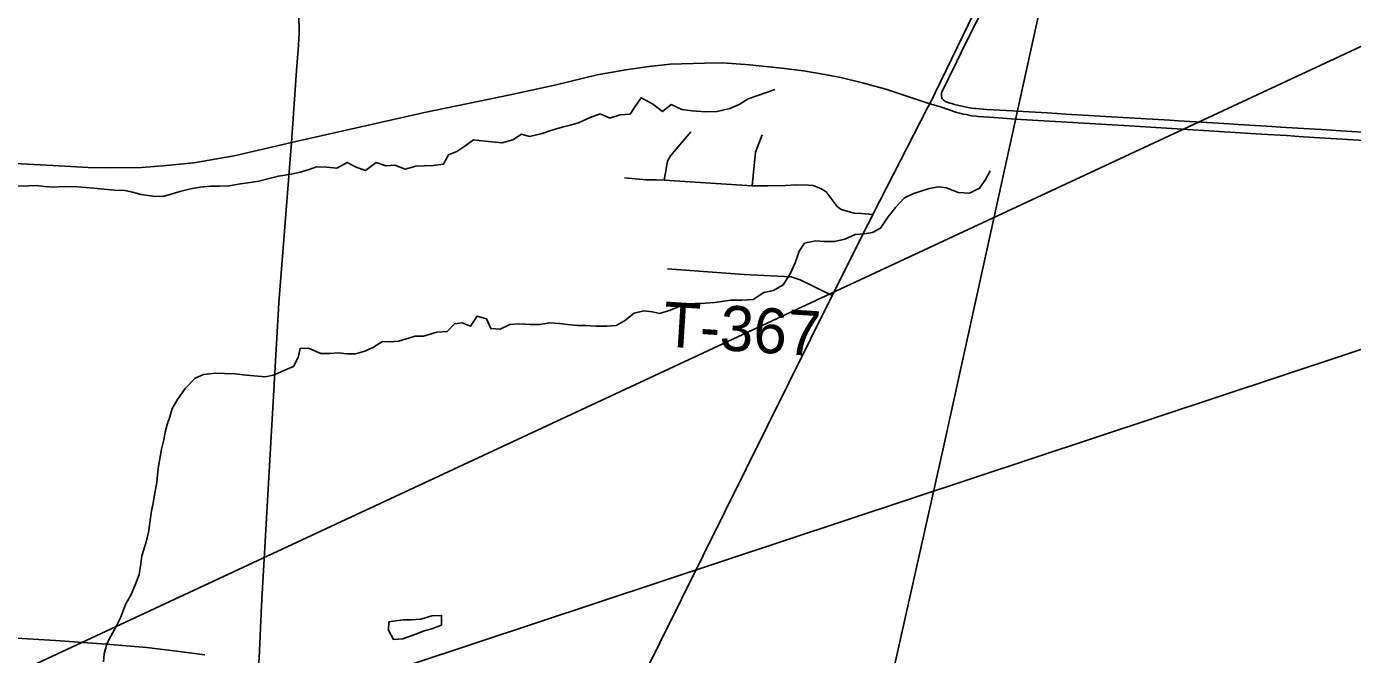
# Model space of a CAD drawing. Extents: x 0 to 34, y 0 to 22.
# Drawn here: x 7.93 to 9.603, y 7.332 to 8.125 of the extents above; entities that cross this region are included whole.
import ezdxf

# ---------------------------------------------------------------- set-up
doc = ezdxf.new("R2010")
doc.units = 0
for name, color, linetype in [('GM_X_City_Street', 7, 'Continuous'), ('GM_X_Corporation', 7, 'Continuous'), ('GM_X_County_Road', 7, 'Continuous'), ('GM_X_Minor_Lake', 7, 'Continuous'), ('GM_X_Minor_River', 7, 'Continuous'), ('GM_X_Rail_Line', 7, 'Continuous'), ('GM_X_State_Route', 7, 'Continuous'), ('GM_X_Township_Road', 7, 'Continuous'), ('GM_X_Township_Road_Text', 7, 'Continuous'), ('SH_Text', 7, 'Continuous')]:
    doc.layers.add(name, color=color, linetype=linetype)

msp = doc.modelspace()

# ---------------------------------------------------------------- linework, layer by layer
at = {"layer": 'GM_X_City_Street'}
for points in [[(8.9746, 7.8897), (8.9836, 7.8891), (8.9982, 7.888)], [(8.8949, 7.809), (8.9064, 7.8054), (8.9466, 7.7856)]]:
    msp.add_lwpolyline(points, dxfattribs=at)
at = {"layer": 'GM_X_Corporation'}
msp.add_lwpolyline([(9.6236, 7.9915), (9.5883, 7.9936), (9.5711, 7.9947), (9.5126, 7.9983), (9.5015, 7.9989), (9.4598, 8.0014), (9.441, 8.0026), (9.384, 8.0061), (9.3731, 8.0068), (9.2923, 8.0117), (9.2419, 8.0147), (9.2305, 8.0154), (9.218, 8.0161), (9.1877, 8.0179), (9.1818, 8.0183), (9.1813, 8.0183), (9.1749, 8.0187), (9.1419, 8.0206), (9.1329, 8.0212), (9.1291, 8.0215), (9.1266, 8.0218), (9.1227, 8.0223), (9.1202, 8.0227), (9.1164, 8.0233), (9.1125, 8.0241), (9.1088, 8.0249), (9.105, 8.0258), (9.1012, 8.0268), (9.0976, 8.0279), (9.0951, 8.0286), (9.0907, 8.0301), (9.0902, 8.0303), (9.0895, 8.0307), (9.0889, 8.031), (9.0882, 8.0316), (9.0877, 8.0319), (9.0872, 8.0325), (9.0864, 8.0334), (9.086, 8.034), (9.0857, 8.0345), (9.0852, 8.0357), (9.085, 8.0362), (9.0848, 8.0369), (9.0847, 8.0381), (9.0846, 8.0387), (9.0846, 8.0394), (9.0847, 8.0402), (9.0848, 8.0409), (9.0849, 8.0414), (9.0852, 8.0422), (9.0856, 8.0431), (9.0937, 8.0597), (9.1042, 8.0812), (9.1152, 8.1037), (9.1431, 8.1596)], dxfattribs=at)
at = {"layer": 'GM_X_County_Road'}
msp.add_line((8.2551, 7.8616), (8.2644, 7.9787), dxfattribs=at)
for points in [[(8.2731, 8.1015), (8.2742, 8.1169), (8.2738, 8.1415), (8.2719, 8.1531), (8.2681, 8.1637), (8.2587, 8.1797), (8.2463, 8.197), (8.2278, 8.2218), (8.2228, 8.2286)], [(8.2644, 7.9787), (8.2708, 8.0698), (8.2731, 8.1015)], [(8.2644, 7.9787), (8.4323, 8.0168), (8.5402, 8.0389), (8.5984, 8.0514), (8.6501, 8.064), (8.6862, 8.0705), (8.7154, 8.0746), (8.7423, 8.0777), (8.7857, 8.0791), (8.8088, 8.0794), (8.8424, 8.0766), (8.8833, 8.0728), (8.9106, 8.0693), (8.9375, 8.0647), (8.9578, 8.0609), (8.9851, 8.0542), (9.0145, 8.0462), (9.0386, 8.0381), (9.0699, 8.0276)], [(7.8672, 7.9559), (7.923, 7.9516), (7.9711, 7.9491), (8.0078, 7.9471), (8.0344, 7.9466), (8.075, 7.9471), (8.1021, 7.9491), (8.1413, 7.9531), (8.1919, 7.9621), (8.2644, 7.9787)], [(8.2165, 7.2479), (8.2194, 7.2772), (8.2237, 7.3274), (8.2266, 7.3943), (8.2484, 7.7765), (8.2551, 7.8616)]]:
    msp.add_lwpolyline(points, dxfattribs=at)
at = {"layer": 'GM_X_Minor_Lake'}
for points in [[(8.4536, 7.3742), (8.4538, 7.3816), (8.4417, 7.3812), (8.4277, 7.377), (8.4152, 7.3762), (8.4054, 7.3762), (8.3872, 7.3736)], [(8.3872, 7.3736), (8.3869, 7.3629), (8.3933, 7.3512), (8.4047, 7.352), (8.4202, 7.3577), (8.4319, 7.3622), (8.4417, 7.3645), (8.4535, 7.3695), (8.4536, 7.3742)]]:
    msp.add_lwpolyline(points, dxfattribs=at)
at = {"layer": 'GM_X_Minor_River'}
for points in [[(7.919, 7.9235), (7.9323, 7.9239), (7.9421, 7.9243), (7.9527, 7.9231), (7.9637, 7.9224), (7.9777, 7.9232), (7.9939, 7.9228), (8.0045, 7.9221), (8.0148, 7.9209), (8.0405, 7.9187), (8.0541, 7.918), (8.0639, 7.9161), (8.0745, 7.9131), (8.0893, 7.9108), (8.1022, 7.9104), (8.1124, 7.9135), (8.1233, 7.9169), (8.137, 7.9204), (8.1491, 7.9223), (8.1623, 7.9238), (8.174, 7.9238), (8.1858, 7.9242), (8.1998, 7.9265), (8.2122, 7.9284), (8.2232, 7.9299), (8.2361, 7.9334), (8.2478, 7.9364), (8.2641, 7.9387), (8.2754, 7.9414), (8.2856, 7.9444), (8.2958, 7.9482), (8.3091, 7.9475), (8.3216, 7.9464), (8.3348, 7.9536), (8.3462, 7.9475), (8.3579, 7.9434), (8.3711, 7.9533), (8.3836, 7.9491), (8.395, 7.9503), (8.4078, 7.945), (8.4215, 7.9488), (8.432, 7.9492), (8.443, 7.9496), (8.4563, 7.9515), (8.4627, 7.9632), (8.4729, 7.9674), (8.4831, 7.9743), (8.4941, 7.9819), (8.5047, 7.9807), (8.5171, 7.9796), (8.53, 7.9785), (8.5436, 7.9819), (8.5546, 7.9891), (8.5648, 7.9865), (8.5807, 7.9903), (8.5928, 7.9945), (8.606, 7.9979), (8.6159, 8.0006), (8.6265, 8.0036), (8.6412, 8.0101), (8.6541, 8.0151), (8.6662, 8.0094), (8.679, 8.0136), (8.6919, 8.0147), (8.6983, 8.0242), (8.7055, 8.0352), (8.7199, 8.0277), (8.7328, 8.0178), (8.7437, 8.0266), (8.757, 8.0205), (8.7702, 8.0186), (8.7869, 8.0175), (8.8016, 8.0179), (8.8175, 8.0217), (8.8296, 8.0267), (8.8406, 8.0339), (8.8542, 8.0385), (8.864, 8.0419), (8.8742, 8.0457)], [(8.7425, 7.7672), (8.7538, 7.7718), (8.7637, 7.7748), (8.7739, 7.7756), (8.7864, 7.776), (8.7985, 7.7768), (8.8189, 7.7798), (8.8329, 7.7795), (8.8469, 7.7806), (8.8605, 7.7894), (8.8726, 7.792), (8.8851, 7.7989), (8.8938, 7.8129), (8.9002, 7.827), (8.9051, 7.8414), (8.9119, 7.8516), (8.9259, 7.8547), (8.9365, 7.8539), (8.9497, 7.8539), (8.9626, 7.8566), (8.9758, 7.8627), (8.9872, 7.8635), (8.9978, 7.865), (9.0076, 7.8707), (9.0163, 7.8832), (9.0269, 7.8965), (9.0382, 7.9087), (9.0484, 7.914), (9.0586, 7.9174), (9.0692, 7.9205), (9.081, 7.9228), (9.0912, 7.9216), (9.1056, 7.9156), (9.1199, 7.9149), (9.1328, 7.921), (9.14, 7.9312), (9.146, 7.943)], [(8.0271, 7.323), (8.0279, 7.3333), (8.0313, 7.3458), (8.0362, 7.3553), (8.0437, 7.3686), (8.0486, 7.3784), (8.0547, 7.3955), (8.0618, 7.408), (8.0675, 7.4209), (8.072, 7.4334), (8.0743, 7.4467), (8.0754, 7.4569), (8.0799, 7.4714), (8.0837, 7.4862), (8.0856, 7.499), (8.0875, 7.5135), (8.0897, 7.5233), (8.092, 7.5366), (8.0946, 7.5495), (8.0954, 7.559), (8.0965, 7.57), (8.0987, 7.5817), (8.1002, 7.5916), (8.1032, 7.6033), (8.1051, 7.6132), (8.1074, 7.6227), (8.1108, 7.6322), (8.1138, 7.6428), (8.1206, 7.6542), (8.13, 7.6682), (8.1429, 7.6811), (8.1535, 7.6857), (8.1686, 7.6876), (8.1796, 7.6872), (8.1928, 7.6865), (8.2038, 7.6854), (8.2167, 7.6842), (8.2318, 7.6827), (8.2424, 7.6854), (8.2537, 7.6904), (8.267, 7.6961), (8.2726, 7.7071), (8.2753, 7.7188), (8.2859, 7.7192), (8.3014, 7.7124), (8.3127, 7.7124), (8.3233, 7.7132), (8.3343, 7.7121), (8.3453, 7.7117), (8.357, 7.7151), (8.368, 7.7205), (8.3793, 7.7273), (8.3891, 7.7269), (8.3994, 7.7281), (8.4107, 7.7311), (8.4205, 7.7342), (8.4308, 7.7342), (8.4478, 7.7391), (8.461, 7.7399), (8.4701, 7.7498), (8.4799, 7.7509), (8.4905, 7.7468), (8.4985, 7.7593), (8.5106, 7.7563), (8.5159, 7.7438), (8.5276, 7.743), (8.5401, 7.7491), (8.5522, 7.7499), (8.5654, 7.7488), (8.5775, 7.7488), (8.5904, 7.7511), (8.6025, 7.75), (8.6127, 7.7488), (8.6252, 7.7477), (8.6351, 7.7477), (8.6483, 7.747), (8.6623, 7.747), (8.674, 7.7478), (8.6846, 7.7535), (8.6967, 7.7634), (8.7092, 7.7664), (8.7194, 7.7649), (8.7292, 7.763), (8.7425, 7.7672)]]:
    msp.add_lwpolyline(points, dxfattribs=at)
at = {"layer": 'GM_X_Rail_Line'}
msp.add_lwpolyline([(8.9712, 7.0765), (9.0871, 7.5941), (9.3068, 8.5932), (9.5523, 9.677), (9.6655, 10.1841)], dxfattribs=at)
at = {"layer": 'GM_X_State_Route'}
for points in [[(9.0699, 8.0276), (9.167, 8.2273), (9.1789, 8.251), (9.1802, 8.2537)], [(8.9922, 7.876), (8.9972, 7.8858), (8.9982, 7.888), (9.0677, 8.0233), (9.0699, 8.0276)], [(8.6758, 7.2394), (8.6817, 7.2507), (8.7024, 7.2926), (8.9466, 7.7856), (8.9922, 7.876)]]:
    msp.add_lwpolyline(points, dxfattribs=at)
at = {"layer": 'GM_X_Township_Road'}
msp.add_line((9.3221, 7.9997), (9.4888, 7.9894), dxfattribs=at)
for points in [[(9.0699, 8.0276), (9.0834, 8.0236), (9.104, 8.0168), (9.1126, 8.0145), (9.1158, 8.0139), (9.1226, 8.0126), (9.1285, 8.0119), (9.131, 8.0116), (9.1511, 8.0102), (9.178, 8.0084), (9.2859, 8.002), (9.3221, 7.9997)], [(8.7347, 7.9311), (8.739, 7.955), (8.7427, 7.9617), (8.7682, 7.9923)], [(8.8458, 7.9241), (8.8498, 7.9667), (8.8585, 7.9886)], [(9.4888, 7.9894), (9.5044, 7.9884), (9.5203, 7.9877), (9.5411, 7.9861), (9.7445, 7.9738), (9.9809, 7.9594), (10.2498, 7.9432), (10.3182, 7.9393)], [(8.6847, 7.9342), (8.7125, 7.9315), (8.7246, 7.9315), (8.7347, 7.9311), (8.8458, 7.9241), (8.8656, 7.9241), (8.8877, 7.9244), (8.9018, 7.9254), (8.9169, 7.9248), (8.923, 7.9244), (8.9324, 7.9207), (8.9394, 7.9164), (8.9532, 7.8979), (8.9582, 7.8942), (8.9746, 7.8897)], [(8.7391, 7.8191), (8.8352, 7.8122), (8.8949, 7.809)], [(7.5076, 7.4187), (7.5164, 7.4178), (7.5658, 7.4087), (7.5704, 7.408), (7.5817, 7.4056), (7.6012, 7.401), (7.6676, 7.3822), (7.7005, 7.3743), (7.7355, 7.3676), (7.825, 7.3584), (7.9664, 7.3498), (8.0303, 7.3454), (8.0817, 7.3412), (8.1191, 7.3364), (8.1548, 7.3318)]]:
    msp.add_lwpolyline(points, dxfattribs=at)
at = {"layer": 'SH_Text'}
msp.add_lwpolyline([(10.7687, 8.6388), (6.7687, 6.7736), (10.7687, 8.1004)], close=True, dxfattribs=at)

# ---------------------------------------------------------------- texts
at = {"layer": 'GM_X_Township_Road_Text'}
msp.add_text('T-367', height=0.05682, rotation=356.3557, dxfattribs=at).set_placement((8.7322, 7.7213))

doc.saveas('drawing.dxf')
